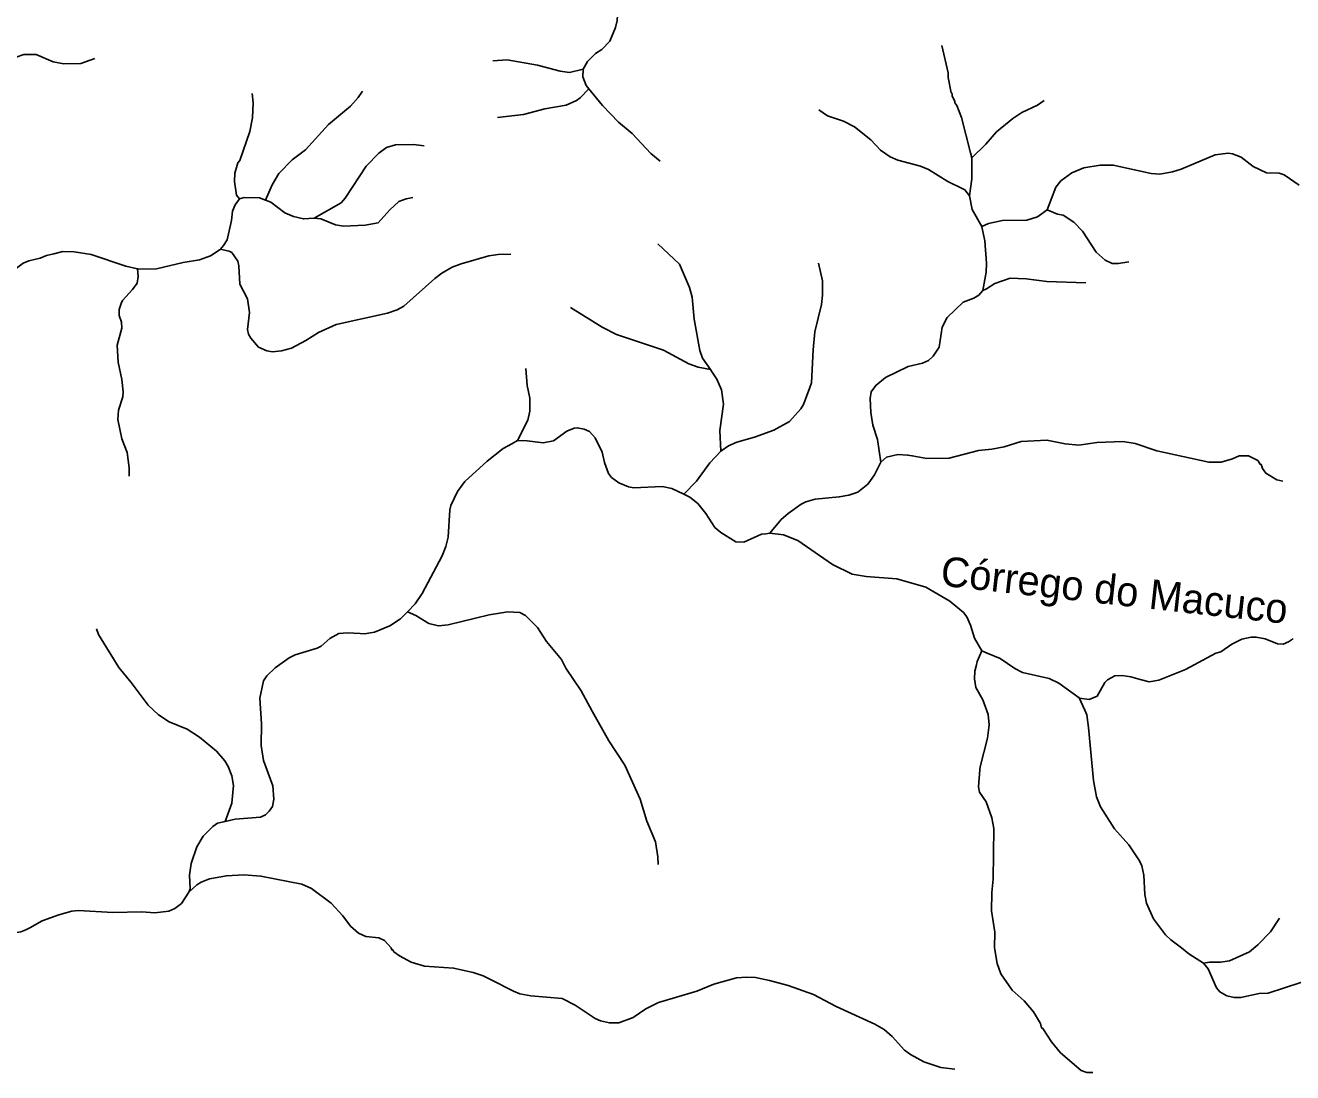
# Model space of a CAD drawing. Extents: x 396 to 422.2, y 7649.8 to 7677.6.
# Drawn here: x 415.262 to 419.533, y 7656.169 to 7659.698 of the extents above; entities that cross this region are included whole.
import ezdxf
from ezdxf.enums import TextEntityAlignment as Align

# ---------------------------------------------------------------- set-up
doc = ezdxf.new("R2010")
doc.units = 0
doc.header["$LTSCALE"] = 0.032
doc.layers.add('61', color=7, linetype='Continuous')
doc.layers.add('7', color=7, linetype='Continuous', lineweight=25)

msp = doc.modelspace()

# ---------------------------------------------------------------- linework, layer by layer
at = {"layer": '7'}
for points in [[(417.1425, 7659.5505), (417.1566, 7659.5771), (417.184, 7659.6037), (417.2048, 7659.6171), (417.2317, 7659.6448), (417.2514, 7659.6915), (417.2561, 7659.715), (417.2624, 7659.8055), (417.2847, 7659.928), (417.2847, 7659.9989), (417.2843, 7660.002), (417.2824, 7660.0158), (417.2455, 7660.1397), (417.2304, 7660.1795), (417.2197, 7660.194)], [(418.3503, 7659.631), (418.3724, 7659.5383), (418.3726, 7659.5229), (418.3821, 7659.4713), (418.3853, 7659.4687), (418.3854, 7659.4597), (418.3949, 7659.4432), (418.395, 7659.4375), (418.4013, 7659.4287), (418.4171, 7659.3879), (418.4472, 7659.2689), (418.4522, 7659.2517)], [(415.4961, 7659.5871), (415.4486, 7659.5694), (415.3922, 7659.5688), (415.3562, 7659.5754), (415.2982, 7659.6005), (415.2575, 7659.6005), (415.2314, 7659.5915), (415.2069, 7659.5666)], [(417.1425, 7659.5505), (417.0959, 7659.5401), (417.064, 7659.5444), (416.9878, 7659.5648), (416.8857, 7659.5822), (416.8375, 7659.5791)], [(417.1608, 7659.485), (417.1521, 7659.4958), (417.1407, 7659.5252), (417.1425, 7659.5505)], [(416.0264, 7659.4683), (416.0295, 7659.4369), (416.0271, 7659.3873), (416.0185, 7659.3406), (415.9848, 7659.2428), (415.9786, 7659.2348), (415.9681, 7659.2003), (415.9665, 7659.1723), (415.9731, 7659.1258), (415.9835, 7659.1135)], [(416.398, 7659.4763), (416.3839, 7659.4556), (416.3579, 7659.4265), (416.2839, 7659.3645), (416.2063, 7659.279), (416.1618, 7659.2455), (416.1161, 7659.1989), (416.0943, 7659.1614), (416.0709, 7659.1096)], [(417.1608, 7659.485), (417.1319, 7659.4541), (417.1197, 7659.4449), (417.0846, 7659.429), (417.0124, 7659.4172), (416.941, 7659.3979), (416.8534, 7659.3877)], [(417.4018, 7659.241), (417.3699, 7659.2662), (417.3066, 7659.334), (417.2614, 7659.372), (417.2066, 7659.4281), (417.1608, 7659.485)], [(418.4437, 7659.1242), (418.4287, 7659.1443), (418.4215, 7659.1477), (418.3704, 7659.1718), (418.3058, 7659.2129), (418.2784, 7659.2241), (418.2026, 7659.2445), (418.1766, 7659.2555), (418.1441, 7659.278), (418.1113, 7659.3131), (418.0559, 7659.3565), (418.0194, 7659.376), (417.9653, 7659.3931), (417.9364, 7659.414)], [(418.4522, 7659.2517), (418.4986, 7659.2976), (418.535, 7659.3396), (418.5897, 7659.385), (418.6199, 7659.4052), (418.6729, 7659.4298), (418.6956, 7659.4452)], [(416.606, 7659.292), (416.5699, 7659.2971), (416.5096, 7659.2959), (416.4797, 7659.2864), (416.4529, 7659.268), (416.4107, 7659.2241), (416.3397, 7659.1165), (416.3264, 7659.1008), (416.2359, 7659.0487)], [(418.4522, 7659.2517), (418.4523, 7659.1816), (418.4474, 7659.1486), (418.4437, 7659.1242)], [(419.5546, 7659.1595), (419.5042, 7659.1946), (419.4874, 7659.2002), (419.4451, 7659.2018), (419.3999, 7659.2222), (419.3595, 7659.2538), (419.3303, 7659.2654), (419.3156, 7659.268), (419.2714, 7659.2622), (419.157, 7659.2137), (419.1286, 7659.205), (419.0859, 7659.1971), (419.0565, 7659.1987), (418.9284, 7659.2273), (418.8838, 7659.2273), (418.8298, 7659.2187), (418.7891, 7659.2012), (418.7516, 7659.1742), (418.7353, 7659.1535), (418.7056, 7659.0763)], [(415.9835, 7659.1135), (415.9696, 7659.0932), (415.9603, 7659.0723), (415.957, 7659.0403), (415.9418, 7658.9761), (415.93, 7658.9562), (415.9195, 7658.9441)], [(416.0709, 7659.1096), (416.0507, 7659.1177), (415.9997, 7659.1187), (415.9835, 7659.1135)], [(416.2359, 7659.0487), (416.1992, 7659.046), (416.1654, 7659.054), (416.1371, 7659.0667), (416.089, 7659.1023), (416.0709, 7659.1096)], [(416.5679, 7659.1182), (416.545, 7659.1138), (416.5202, 7659.1049), (416.4902, 7659.0764), (416.4506, 7659.0328), (416.4072, 7659.0255), (416.3337, 7659.0218), (416.307, 7659.0264), (416.2584, 7659.0461), (416.2359, 7659.0487)], [(418.4437, 7659.1242), (418.4533, 7659.0783), (418.4856, 7659.02)], [(418.7056, 7659.0763), (418.6734, 7659.0527), (418.637, 7659.0423), (418.5553, 7659.0406), (418.5081, 7659.0303), (418.4856, 7659.02)], [(418.9811, 7658.9013), (418.9457, 7658.8959), (418.9252, 7658.8964), (418.9008, 7658.9066), (418.8705, 7658.9345), (418.8253, 7659.0043), (418.796, 7659.0351), (418.7601, 7659.0582), (418.741, 7659.0623), (418.7056, 7659.0763)], [(418.4856, 7659.02), (418.4854, 7659.0199), (418.4955, 7658.9725), (418.5017, 7658.8968), (418.5, 7658.867), (418.4884, 7658.8045)], [(415.6395, 7658.878), (415.6009, 7658.887), (415.4837, 7658.926), (415.427, 7658.9354), (415.388, 7658.9362), (415.358, 7658.9288), (415.3334, 7658.9228), (415.3121, 7658.9133), (415.2735, 7658.9051), (415.2544, 7658.8972), (415.2176, 7658.8684), (415.1813, 7658.8463), (415.1435, 7658.8414), (415.1105, 7658.8421)], [(415.9195, 7658.9441), (415.912, 7658.939), (415.8865, 7658.9215), (415.8485, 7658.9086), (415.7943, 7658.8994), (415.7035, 7658.8776), (415.643, 7658.8772), (415.6395, 7658.878)], [(416.8981, 7658.9268), (416.855, 7658.9267), (416.8235, 7658.9219), (416.7303, 7658.8947), (416.7001, 7658.8831), (416.6658, 7658.8635), (416.6418, 7658.845), (416.5381, 7658.7517), (416.5148, 7658.7397), (416.4822, 7658.7281), (416.3099, 7658.6905), (416.2499, 7658.6629), (416.2072, 7658.636), (416.159, 7658.611), (416.1255, 7658.6018), (416.0946, 7658.5982), (416.0755, 7658.6017), (416.0482, 7658.6144), (416.0221, 7658.6438), (416.0139, 7658.658), (416.0104, 7658.6738), (416.0175, 7658.7302), (416.0102, 7658.777), (415.9849, 7658.8262), (415.9816, 7658.8884), (415.9777, 7658.904), (415.9577, 7658.9331), (415.949, 7658.9375), (415.9329, 7658.9411), (415.9195, 7658.9441)], [(417.3941, 7658.9627), (417.4664, 7658.8935), (417.5, 7658.8154), (417.5098, 7658.7824), (417.5161, 7658.7079), (417.5353, 7658.6022), (417.5441, 7658.577), (417.5706, 7658.5381)], [(417.9356, 7658.8973), (417.9483, 7658.8374), (417.9483, 7658.7892), (417.9451, 7658.7576), (417.9228, 7658.6655), (417.917, 7658.6045), (417.9117, 7658.4932), (417.9058, 7658.4775), (417.8845, 7658.4211), (417.8757, 7658.4056), (417.8369, 7658.3639), (417.784, 7658.3341), (417.7199, 7658.3101), (417.6593, 7658.2941), (417.632, 7658.2809), (417.6061, 7658.2632)], [(415.6395, 7658.878), (415.6419, 7658.8519), (415.6387, 7658.8298), (415.6228, 7658.8078), (415.5896, 7658.7714), (415.5846, 7658.7606), (415.5782, 7658.7414), (415.5782, 7658.721), (415.5861, 7658.6978), (415.5869, 7658.6776), (415.5718, 7658.6208), (415.5749, 7658.5634), (415.587, 7658.5053), (415.5917, 7658.4638), (415.5906, 7658.4469), (415.5757, 7658.4016), (415.5734, 7658.3697), (415.5872, 7658.3055), (415.6052, 7658.2591), (415.6124, 7658.2077), (415.6117, 7658.1795)], [(418.836, 7658.8311), (418.7047, 7658.8357), (418.6345, 7658.8445), (418.5815, 7658.8461), (418.5293, 7658.8288), (418.5014, 7658.8101), (418.4884, 7658.8045)], [(418.4884, 7658.8045), (418.475, 7658.7895), (418.4582, 7658.7794), (418.4221, 7658.7657), (418.3685, 7658.7143), (418.3515, 7658.6813), (418.3421, 7658.6142), (418.3216, 7658.5841), (418.3062, 7658.5692), (418.2856, 7658.5601), (418.2367, 7658.5485), (418.1611, 7658.5116), (418.1279, 7658.485), (418.1125, 7658.4638), (418.1087, 7658.4406), (418.1109, 7658.394), (418.1181, 7658.3513), (418.1335, 7658.3023), (418.1452, 7658.2262)], [(417.099, 7658.7473), (417.2055, 7658.6812), (417.2542, 7658.6565), (417.4127, 7658.6036), (417.4978, 7658.5577), (417.5299, 7658.5461), (417.5706, 7658.5381)], [(416.9483, 7658.5416), (416.9531, 7658.4846), (416.9626, 7658.4418), (416.9626, 7658.3984), (416.9559, 7658.3677), (416.921, 7658.2992)], [(417.5706, 7658.5381), (417.574, 7658.5331), (417.5924, 7658.506), (417.6086, 7658.4702), (417.615, 7658.4217), (417.6022, 7658.3336), (417.6061, 7658.2632)], [(417.4807, 7658.1187), (417.4411, 7658.1379), (417.4078, 7658.1443), (417.3132, 7658.1396), (417.2945, 7658.1432), (417.2619, 7658.157), (417.237, 7658.1749), (417.2271, 7658.1887), (417.2142, 7658.2251), (417.2065, 7658.2604), (417.1825, 7658.3081), (417.1629, 7658.3292), (417.1449, 7658.3374), (417.1221, 7658.3421), (417.1118, 7658.3413), (417.0864, 7658.3305), (417.0416, 7658.2988), (417.0076, 7658.292), (416.9535, 7658.2988), (416.921, 7658.2992)], [(416.921, 7658.2992), (416.9015, 7658.2885), (416.872, 7658.2726), (416.8183, 7658.2296), (416.7432, 7658.1609), (416.7181, 7658.1277), (416.6965, 7658.0805), (416.6931, 7658.0658), (416.6865, 7657.9738), (416.6792, 7657.9419), (416.6666, 7657.9104), (416.5999, 7657.7834), (416.5755, 7657.7493), (416.5496, 7657.7218)], [(418.1452, 7658.2262), (418.1643, 7658.2427), (418.2028, 7658.252), (418.2351, 7658.2505), (418.2512, 7658.2477), (418.2996, 7658.2392), (418.3749, 7658.2401), (418.4739, 7658.2654), (418.519, 7658.2697), (418.5612, 7658.2776), (418.6182, 7658.2958), (418.7047, 7658.3006), (418.7662, 7658.288), (418.8122, 7658.284), (418.8731, 7658.2927), (418.9608, 7658.2958), (419.0023, 7658.2888), (419.0756, 7658.2644), (419.2502, 7658.2265), (419.2925, 7658.2265), (419.3303, 7658.2371), (419.3532, 7658.2473), (419.3843, 7658.248), (419.4156, 7658.232), (419.4233, 7658.2199), (419.4269, 7658.219), (419.4319, 7658.2055), (419.4426, 7658.1896), (419.4792, 7658.1669), (419.4995, 7658.162)], [(417.6061, 7658.2632), (417.5684, 7658.2244), (417.5241, 7658.1625), (417.4807, 7658.1187)], [(418.1452, 7658.2262), (418.1243, 7658.1842), (418.1105, 7658.1645), (418.1016, 7658.1517), (418.0679, 7658.1253), (418.0368, 7658.115), (418.0049, 7658.1093), (417.9236, 7658.102), (417.8921, 7658.0924), (417.8768, 7658.0847), (417.8332, 7658.0539), (417.8097, 7658.0329), (417.7715, 7657.987)], [(417.7715, 7657.987), (417.7573, 7657.9851), (417.7431, 7657.9832), (417.6839, 7657.9563), (417.6569, 7657.9579), (417.6054, 7657.9891), (417.5853, 7658.0066), (417.5549, 7658.0529), (417.5283, 7658.0865), (417.502, 7658.1083), (417.4807, 7658.1187)], [(418.4855, 7657.591), (418.4606, 7657.633), (418.447, 7657.6775), (418.4347, 7657.7049), (418.4234, 7657.7196), (418.3777, 7657.7576), (418.2968, 7657.8051), (418.1987, 7657.8333), (418.0961, 7657.8415), (418.0482, 7657.8487), (417.9818, 7657.8811), (417.8653, 7657.9629), (417.8172, 7657.9813), (417.7715, 7657.987)], [(416.5496, 7657.7218), (416.5268, 7657.6986), (416.4907, 7657.6747), (416.4391, 7657.6531), (416.4047, 7657.6476), (416.3901, 7657.6486), (416.3482, 7657.6516), (416.3185, 7657.6493), (416.2886, 7657.632), (416.2595, 7657.6063), (416.2453, 7657.599), (416.1715, 7657.5773), (416.1516, 7657.5672), (416.1037, 7657.5334), (416.076, 7657.5066), (416.0648, 7657.4891), (416.0519, 7657.431), (416.0582, 7657.3443), (416.0567, 7657.2719), (416.0649, 7657.2209), (416.0957, 7657.1355), (416.0998, 7657.0906), (416.095, 7657.0657), (416.0839, 7657.0497), (416.0713, 7657.0383), (416.0549, 7657.0303), (415.9689, 7657.023), (415.9357, 7657.0154)], [(416.5496, 7657.7218), (416.5782, 7657.7097), (416.6216, 7657.6824), (416.6544, 7657.6747), (416.6869, 7657.6779), (416.8249, 7657.7117), (416.8877, 7657.7217), (416.9286, 7657.7192), (416.9472, 7657.7093), (416.9886, 7657.6692), (417.0187, 7657.6218), (417.0688, 7657.5611), (417.0834, 7657.5321), (417.135, 7657.4558), (417.1728, 7657.3872), (417.2282, 7657.2867), (417.282, 7657.2048), (417.3337, 7657.0905), (417.3568, 7657.0168), (417.3858, 7656.9465), (417.394, 7656.8963), (417.3949, 7656.87)], [(415.5017, 7657.6643), (415.5081, 7657.6456), (415.5768, 7657.5339), (415.6186, 7657.4833), (415.6757, 7657.4072), (415.7108, 7657.375), (415.7462, 7657.3518), (415.8075, 7657.3263), (415.8487, 7657.2995), (415.9065, 7657.2521), (415.9343, 7657.2193), (415.9451, 7657.2006), (415.9576, 7657.1694), (415.9641, 7657.1371), (415.9574, 7657.0768), (415.9357, 7657.0154)], [(419.5338, 7657.6326), (419.5322, 7657.6302), (419.5185, 7657.6204), (419.5006, 7657.6129), (419.482, 7657.6141), (419.4409, 7657.6308), (419.4097, 7657.6363), (419.393, 7657.6363), (419.3614, 7657.6299), (419.3282, 7657.6134), (419.2905, 7657.5874), (419.2746, 7657.5826), (419.1719, 7657.528), (419.0822, 7657.4922)], [(418.4855, 7657.591), (418.47, 7657.555), (418.4665, 7657.5392), (418.4623, 7657.5215), (418.4604, 7657.4957), (418.4651, 7657.4665), (418.4892, 7657.4255), (418.5065, 7657.3763), (418.5105, 7657.3414), (418.5051, 7657.2958), (418.4794, 7657.1993), (418.4787, 7657.1895), (418.4747, 7657.132), (418.478, 7657.1145), (418.5, 7657.0813), (418.5192, 7657.0274), (418.5264, 7656.992), (418.5241, 7656.8215), (418.5194, 7656.7758), (418.5177, 7656.7147), (418.5289, 7656.6423), (418.5281, 7656.5897), (418.5369, 7656.5371), (418.5498, 7656.502), (418.5874, 7656.447), (418.6284, 7656.4115), (418.6598, 7656.3745), (418.6835, 7656.3348), (418.6863, 7656.3205), (418.6914, 7656.318), (418.72, 7656.2729), (418.7505, 7656.2359), (418.8199, 7656.1762), (418.8392, 7656.1699), (418.8599, 7656.169)], [(418.8133, 7657.4318), (418.7449, 7657.482), (418.7127, 7657.4974), (418.6231, 7657.5173), (418.5965, 7657.5314), (418.5472, 7657.5645), (418.503, 7657.5831), (418.4855, 7657.591)], [(419.0822, 7657.4922), (419.0497, 7657.4865), (419.0195, 7657.4938), (418.9875, 7657.5032), (418.9579, 7657.5079), (418.9342, 7657.5068), (418.9094, 7657.4923), (418.9, 7657.4834), (418.8743, 7657.4381), (418.8476, 7657.4267), (418.8142, 7657.4312), (418.8133, 7657.4318)], [(419.2327, 7656.5376), (419.1827, 7656.5689), (419.1587, 7656.5901), (419.1225, 7656.6169), (419.1045, 7656.6333), (419.0641, 7656.6876), (419.0405, 7656.7397), (419.0346, 7656.7699), (419.0312, 7656.8348), (419.025, 7656.8656), (419.0171, 7656.8832), (418.9813, 7656.9368), (418.933, 7656.9907), (418.8855, 7657.065), (418.8723, 7657.099), (418.8622, 7657.1534), (418.845, 7657.3327), (418.8399, 7657.3744), (418.8331, 7657.3902), (418.8133, 7657.4318)], [(415.9357, 7657.0154), (415.9098, 7657.0094), (415.8939, 7656.9991), (415.8615, 7656.9655), (415.8401, 7656.9305), (415.821, 7656.8738), (415.8151, 7656.8348), (415.8172, 7656.7886), (415.8132, 7656.7767)], [(415.8132, 7656.7767), (415.8395, 7656.8019), (415.8541, 7656.8109), (415.8828, 7656.8221), (415.9395, 7656.8324), (415.9989, 7656.8356), (416.0558, 7656.8316), (416.1942, 7656.8044), (416.2262, 7656.7896), (416.2922, 7656.7405), (416.3323, 7656.6972), (416.3582, 7656.6632), (416.3846, 7656.6387), (416.4091, 7656.6276), (416.4529, 7656.6228), (416.4726, 7656.6141), (416.4953, 7656.5896), (416.4968, 7656.5833), (416.5004, 7656.5825), (416.5042, 7656.5765), (416.5234, 7656.5623), (416.5626, 7656.541), (416.6069, 7656.5283), (416.7055, 7656.5215), (416.7718, 7656.5065), (416.805, 7656.4958), (416.8319, 7656.4819), (416.9068, 7656.4432), (416.9288, 7656.435), (416.9659, 7656.4278), (417.071, 7656.4185), (417.1152, 7656.3962), (417.182, 7656.3519), (417.2, 7656.344), (417.2302, 7656.3365), (417.2624, 7656.3373), (417.31, 7656.3546), (417.3536, 7656.3836), (417.3961, 7656.4057), (417.5249, 7656.4439), (417.5823, 7656.467), (417.6584, 7656.488), (417.6934, 7656.4912), (417.7222, 7656.4895), (417.77, 7656.4799), (417.8326, 7656.4622), (417.9183, 7656.432), (417.9941, 7656.3924), (418.1244, 7656.3329), (418.1559, 7656.3139), (418.1832, 7656.2911), (418.2253, 7656.2445), (418.2454, 7656.2297), (418.2896, 7656.2056), (418.3478, 7656.1864), (418.3942, 7656.1802)], [(415.8132, 7656.7767), (415.788, 7656.7392), (415.766, 7656.7223), (415.7457, 7656.7135), (415.698, 7656.7081), (415.655, 7656.7105), (415.5565, 7656.7088), (415.4416, 7656.716), (415.419, 7656.7137), (415.3751, 7656.7012), (415.3188, 7656.6804), (415.2769, 7656.6573), (415.2637, 7656.6501), (415.2467, 7656.6437), (415.226, 7656.6403), (415.1998, 7656.6419), (415.1749, 7656.6497), (415.0995, 7656.695), (415.0604, 7656.7117), (415.01, 7656.7201), (414.944, 7656.7256), (414.8533, 7656.7231), (414.7985, 7656.7113), (414.7688, 7656.7068)], [(419.4883, 7656.6898), (419.4579, 7656.6441), (419.4159, 7656.5999), (419.3875, 7656.5767), (419.3197, 7656.5453), (419.2902, 7656.5408), (419.2527, 7656.5413), (419.2327, 7656.5376)], [(419.7173, 7656.4738), (419.7114, 7656.4749), (419.6521, 7656.4757), (419.6378, 7656.4783), (419.586, 7656.4775), (419.5605, 7656.4728), (419.4502, 7656.4371), (419.4205, 7656.4353), (419.3587, 7656.4224), (419.3363, 7656.4225), (419.3116, 7656.4278), (419.2875, 7656.4412), (419.2766, 7656.4543), (419.2479, 7656.5185), (419.2327, 7656.5376)]]:
    msp.add_lwpolyline(points, dxfattribs=at)

# ---------------------------------------------------------------- texts
at = {"layer": '61'}
msp.add_text('Córrego do Macuco', height=0.1, rotation=353.675, dxfattribs=at).set_placement((418.927, 7657.7461), align=Align.CENTER)

doc.saveas('drawing.dxf')
